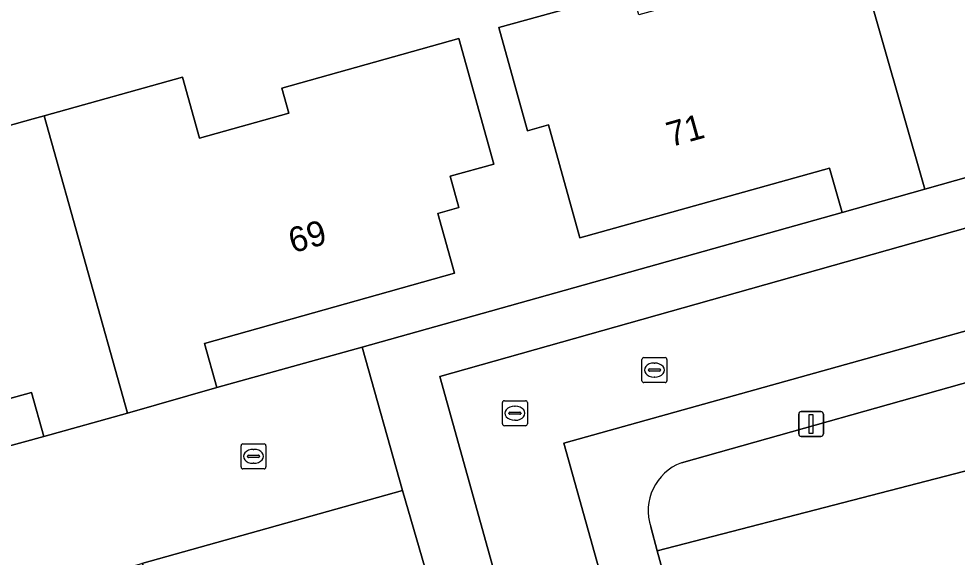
# Model space of a CAD drawing. Extents: x 159626 to 160723, y 388173 to 389416.
# Drawn here: x 159837.12 to 159874.74, y 388448.77 to 388470.35 of the extents above; entities that cross this region are included whole.
import ezdxf

# ---------------------------------------------------------------- set-up
doc = ezdxf.new("R2010")
doc.units = 0
for name, color, linetype in [('IMGEO_Erf', 7, 'Continuous'), ('IMGEO_Groenvoorziening', 7, 'Continuous'), ('IMGEO_Kolk', 7, 'Continuous'), ('IMGEO_Lichtmast', 7, 'Continuous'), ('IMGEO_Pand', 7, 'Continuous'), ('IMGEO_Pand_nummerreeks', 7, 'Continuous'), ('IMGEO_Rijbaan_lokaal_open', 7, 'Continuous'), ('IMGEO_Rioolput', 7, 'Continuous'), ('IMGEO_Voetpad_open', 7, 'Continuous')]:
    doc.layers.add(name, color=color, linetype=linetype)

msp = doc.modelspace()

# ---------------------------------------------------------------- linework, layer by layer
at = {"layer": 'IMGEO_Erf'}
for points in [[(159832.881, 388464.987), (159837.696, 388466.335), (159838.145, 388466.461), (159843.685, 388468.012), (159844.37, 388465.564), (159847.946, 388466.564), (159847.664, 388467.566), (159854.756, 388469.551), (159856.163, 388464.528), (159854.41, 388464.037), (159854.76, 388462.785), (159853.92, 388462.55), (159854.591, 388460.15), (159844.567, 388457.342), (159845.063, 388455.568), (159850.882, 388457.196), (159870.121, 388462.581), (159869.615, 388464.359), (159859.613, 388461.567), (159858.355, 388466.092), (159857.517, 388465.859), (159856.365, 388469.998), (159861.708, 388471.483)], [(159894.206, 388461.135), (159890.882, 388460.201), (159881.289, 388457.505), (159876.398, 388456.13), (159863.681, 388452.556)], [(159819.193, 388448.425), (159838.132, 388453.605), (159837.634, 388455.378), (159823.372, 388451.431)], [(159862.457, 388449.987), (159862.717, 388449.025), (159879.836, 388453.469)]]:
    msp.add_lwpolyline(points, dxfattribs=at)
msp.add_arc((159864.399, 388450.638), 2.048, 110.5157, 198.5333, dxfattribs=at)
at = {"layer": 'IMGEO_Groenvoorziening'}
msp.add_lwpolyline([(159856.782, 388436.748), (159852.499, 388451.444), (159842.058, 388448.523), (159844.146, 388445.771)], dxfattribs=at)
at = {"layer": 'IMGEO_Kolk'}
for p, q in [((159862.102, 388455.847), (159862.102, 388456.699)), ((159862.177, 388456.773), (159863.029, 388456.773)), ((159863.103, 388456.699), (159863.103, 388455.847)), ((159862.361, 388456.267), (159862.361, 388456.279)), ((159862.404, 388456.316), (159862.802, 388456.316)), ((159862.59, 388456.553), (159862.615, 388456.553)), ((159862.845, 388456.279), (159862.845, 388456.267)), ((159862.799, 388456.23), (159862.401, 388456.23)), ((159862.613, 388455.993), (159862.588, 388455.993)), ((159863.029, 388455.773), (159862.177, 388455.773)), ((159846.031, 388452.39), (159846.031, 388453.242)), ((159846.106, 388453.316), (159846.958, 388453.316)), ((159847.032, 388453.242), (159847.032, 388452.39)), ((159846.333, 388452.859), (159846.731, 388452.859)), ((159846.519, 388453.096), (159846.544, 388453.096)), ((159846.29, 388452.81), (159846.29, 388452.822)), ((159846.728, 388452.773), (159846.33, 388452.773)), ((159846.542, 388452.536), (159846.517, 388452.536)), ((159846.774, 388452.822), (159846.774, 388452.81)), ((159846.958, 388452.316), (159846.106, 388452.316))]:
    msp.add_line(p, q, dxfattribs=at)
for points in [[(159862.102, 388455.847), (159862.102, 388456.699)], [(159862.177, 388456.773), (159863.029, 388456.773)], [(159863.103, 388456.699), (159863.103, 388455.847)], [(159863.029, 388455.773), (159862.177, 388455.773)], [(159846.031, 388452.39), (159846.031, 388453.242)], [(159846.106, 388453.316), (159846.958, 388453.316)], [(159847.032, 388453.242), (159847.032, 388452.39)], [(159846.958, 388452.316), (159846.106, 388452.316)]]:
    msp.add_lwpolyline(points, dxfattribs=at)
for centre, radius, start, end in [((159862.179, 388456.697), 0.0765, 91.552, 178.448), ((159862.179, 388456.697), 0.0765, 91.552, 178.448), ((159863.027, 388456.697), 0.0765, 1.552, 88.448), ((159863.027, 388456.697), 0.0765, 1.552, 88.448), ((159862.401, 388456.276), 0.0403, 85.8775, 175.7526), ((159862.398, 388456.266), 0.0366, 178.938, 274.7102), ((159862.802, 388456.273), 0.043, 264.8664, 352.4533), ((159862.806, 388456.278), 0.0386, 1.7309, 96.639), ((159862.179, 388455.849), 0.0765, 181.552, 268.448), ((159862.179, 388455.849), 0.0765, 181.552, 268.448), ((159863.027, 388455.849), 0.0765, 271.552, 358.448), ((159863.027, 388455.849), 0.0765, 271.552, 358.448), ((159846.108, 388453.24), 0.0765, 91.552, 178.448), ((159846.108, 388453.24), 0.0765, 91.552, 178.448), ((159846.956, 388453.24), 0.0765, 1.552, 88.448), ((159846.956, 388453.24), 0.0765, 1.552, 88.448), ((159846.33, 388452.819), 0.0403, 85.8775, 175.7526), ((159846.735, 388452.821), 0.0386, 1.7309, 96.639), ((159846.327, 388452.809), 0.0366, 178.938, 274.7102), ((159846.731, 388452.816), 0.043, 264.8664, 352.4533), ((159846.108, 388452.392), 0.0765, 181.552, 268.448), ((159846.108, 388452.392), 0.0765, 181.552, 268.448), ((159846.956, 388452.392), 0.0765, 271.552, 358.448), ((159846.956, 388452.392), 0.0765, 271.552, 358.448)]:
    msp.add_arc(centre, radius, start, end, dxfattribs=at)
for centre, major_axis, ratio, start_param, end_param in [((159862.589, 388456.273), (-0.387, 0.002), 0.722429, 4.712389, 7.853982), ((159862.614, 388456.273), (-0.39, 0.002), 0.717154, 1.570796, 4.712389), ((159846.518, 388452.816), (-0.387, 0.002), 0.722429, 4.712389, 7.853982), ((159846.543, 388452.816), (-0.39, 0.002), 0.717154, 1.570796, 4.712389)]:
    msp.add_ellipse(centre, major_axis=major_axis, ratio=ratio, start_param=start_param, end_param=end_param, dxfattribs=at)
at = {"layer": 'IMGEO_Lichtmast'}
for p, q in [((159868.384, 388453.712), (159868.384, 388454.512)), ((159868.384, 388454.512), (159868.384, 388453.712)), ((159868.484, 388454.612), (159869.274, 388454.612)), ((159869.274, 388454.612), (159868.484, 388454.612)), ((159869.374, 388454.512), (159869.374, 388453.712)), ((159869.374, 388453.712), (159869.374, 388454.512)), ((159869.274, 388453.612), (159868.484, 388453.612)), ((159868.484, 388453.612), (159869.274, 388453.612))]:
    msp.add_line(p, q, dxfattribs=at)
msp.add_lwpolyline([(159868.804, 388454.487), (159868.954, 388454.487), (159868.954, 388453.737), (159868.804, 388453.737), (159868.804, 388454.487)], dxfattribs=at)
for centre, start, end in [((159868.484, 388454.512), 90, 180), ((159868.484, 388454.512), 90, 180), ((159869.274, 388454.512), 0, 90), ((159869.274, 388454.512), 360, 90), ((159868.484, 388453.712), 180, 270), ((159868.484, 388453.712), 180, 270), ((159869.274, 388453.712), 270, 0), ((159869.274, 388453.712), 270, 0)]:
    msp.add_arc(centre, 0.1, start, end, dxfattribs=at)
at = {"layer": 'IMGEO_Pand'}
for points in [[(159870.052, 388475.377), (159873.439, 388463.52), (159877.039, 388464.539), (159876.552, 388466.292), (159886.556, 388469.073), (159885.3, 388473.598), (159886.138, 388473.831), (159884.99, 388477.962), (159879.657, 388476.48), (159879.933, 388475.489), (159876.343, 388474.49), (159875.663, 388476.937), (159870.846, 388475.598)], [(159870.052, 388475.377), (159864.871, 388473.937), (159865.552, 388471.493), (159861.98, 388470.501), (159861.708, 388471.483), (159856.365, 388469.998), (159857.517, 388465.859), (159858.355, 388466.092), (159859.613, 388461.567), (159869.615, 388464.359), (159870.121, 388462.581), (159873.439, 388463.52)], [(159841.477, 388454.552), (159845.063, 388455.568), (159844.567, 388457.342), (159854.591, 388460.15), (159853.92, 388462.55), (159854.76, 388462.785), (159854.41, 388464.037), (159856.163, 388464.528), (159854.756, 388469.551), (159847.664, 388467.566), (159847.946, 388466.564), (159844.37, 388465.564), (159843.685, 388468.012), (159838.145, 388466.461)], [(159841.477, 388454.552), (159838.145, 388466.461), (159837.696, 388466.335), (159832.881, 388464.987), (159832.487, 388466.391), (159828.906, 388465.387), (159824.145, 388464.052), (159824.948, 388461.189), (159824.359, 388461.024), (159824.966, 388458.858), (159821.576, 388457.92), (159823.372, 388451.431), (159837.634, 388455.378), (159838.132, 388453.605)], [(159863.708, 388445.396), (159865.486, 388445.857), (159868.091, 388435.822), (159872.633, 388437.002), (159872.849, 388436.17), (159876.985, 388437.244), (159875.591, 388442.607), (159877.74, 388443.164), (159876.811, 388446.741), (159881.283, 388447.902), (159881.094, 388448.63), (159879.836, 388453.469), (159862.717, 388449.025)]]:
    msp.add_lwpolyline(points, close=True, dxfattribs=at)
at = {"layer": 'IMGEO_Rijbaan_lokaal_open'}
msp.add_lwpolyline([(159871.183, 388409.697), (159858.976, 388453.345), (159890.351, 388462.109), (159889.278, 388465.962), (159854.007, 388456.02), (159867.243, 388408.503)], close=True, dxfattribs=at)
msp.add_lwpolyline([(159826.869, 388444.275), (159840.008, 388447.95), (159842.058, 388448.523), (159852.499, 388451.444), (159850.882, 388457.196), (159845.063, 388455.568), (159841.477, 388454.552), (159838.132, 388453.605), (159819.193, 388448.425)], dxfattribs=at)
at = {"layer": 'IMGEO_Rioolput'}
for p, q in [((159856.511, 388454.116), (159856.511, 388454.968)), ((159856.586, 388455.042), (159857.438, 388455.042)), ((159856.999, 388454.822), (159857.024, 388454.822)), ((159857.512, 388454.968), (159857.512, 388454.116)), ((159856.77, 388454.536), (159856.77, 388454.548)), ((159857.208, 388454.499), (159856.81, 388454.499)), ((159856.813, 388454.585), (159857.211, 388454.585)), ((159857.254, 388454.548), (159857.254, 388454.536)), ((159857.438, 388454.042), (159856.586, 388454.042)), ((159857.022, 388454.262), (159856.997, 388454.262))]:
    msp.add_line(p, q, dxfattribs=at)
for points in [[(159856.511, 388454.116), (159856.511, 388454.968)], [(159856.586, 388455.042), (159857.438, 388455.042)], [(159857.512, 388454.968), (159857.512, 388454.116)], [(159857.438, 388454.042), (159856.586, 388454.042)]]:
    msp.add_lwpolyline(points, dxfattribs=at)
for centre, radius, start, end in [((159856.588, 388454.966), 0.0765, 91.552, 178.448), ((159856.588, 388454.966), 0.0765, 91.552, 178.448), ((159857.436, 388454.966), 0.0765, 1.552, 88.448), ((159857.436, 388454.966), 0.0765, 1.552, 88.448), ((159856.81, 388454.545), 0.0403, 85.8775, 175.7526), ((159856.807, 388454.535), 0.0366, 178.938, 274.7102), ((159857.211, 388454.542), 0.043, 264.8664, 352.4533), ((159857.215, 388454.547), 0.0386, 1.7309, 96.639), ((159856.588, 388454.118), 0.0765, 181.552, 268.448), ((159856.588, 388454.118), 0.0765, 181.552, 268.448), ((159857.436, 388454.118), 0.0765, 271.552, 358.448), ((159857.436, 388454.118), 0.0765, 271.552, 358.448)]:
    msp.add_arc(centre, radius, start, end, dxfattribs=at)
for centre, major_axis, ratio, start_param, end_param in [((159856.998, 388454.542), (-0.387, 0.002), 0.722429, 4.712389, 7.853982), ((159857.023, 388454.542), (-0.39, 0.002), 0.717154, 1.570796, 4.712389)]:
    msp.add_ellipse(centre, major_axis=major_axis, ratio=ratio, start_param=start_param, end_param=end_param, dxfattribs=at)
at = {"layer": 'IMGEO_Voetpad_open'}
for points in [[(159890.763, 388466.088), (159889.278, 388465.962), (159890.351, 388462.109), (159858.976, 388453.345), (159871.183, 388409.697), (159871.974, 388406.867), (159883.064, 388367.211), (159868.371, 388363.142), (159877.583, 388329.947), (159898.714, 388335.876), (159901.439, 388336.64), (159939.056, 388347.194), (159938.495, 388349.196), (159935.001, 388348.184)], [(159877.981, 388369.955), (159868.033, 388405.666), (159867.243, 388408.503), (159854.007, 388456.02), (159889.278, 388465.962)], [(159877.039, 388464.539), (159873.439, 388463.52), (159870.121, 388462.581), (159850.882, 388457.196), (159852.499, 388451.444), (159856.782, 388436.748), (159858.925, 388429.04), (159860.545, 388423.261), (159861.857, 388418.591), (159861.923, 388418.609), (159863.885, 388411.505), (159866.166, 388403.253), (159869.862, 388390.097), (159870.943, 388386.198), (159871.789, 388383.149), (159874.651, 388372.898)], [(159863.681, 388452.556), (159876.398, 388456.13), (159881.289, 388457.505), (159890.882, 388460.201), (159894.206, 388461.135)], [(159872.396, 388362.2), (159916.97, 388374.672), (159922.592, 388376.25), (159928.443, 388377.878), (159927.612, 388380.783), (159906.895, 388374.924), (159895.473, 388371.693), (159891.335, 388370.601), (159885.125, 388368.905), (159881.588, 388381.462), (159880.723, 388384.547), (159879.649, 388388.378), (159872.648, 388413.43), (159871.81, 388416.443), (159870.719, 388420.363), (159863.708, 388445.396), (159862.717, 388449.025), (159862.457, 388449.987)]]:
    msp.add_lwpolyline(points, dxfattribs=at)
msp.add_arc((159864.399, 388450.638), 2.048, 110.5157, 198.5333, dxfattribs=at)

# ---------------------------------------------------------------- texts
at = {"layer": 'IMGEO_Pand_nummerreeks'}
for s, rotation, p in [('71', 15.5968, (159863.249, 388465.198)), ('69', 15.649, (159848.104, 388460.95))]:
    msp.add_text(s, height=1, rotation=rotation, dxfattribs=at).set_placement(p)

doc.saveas('drawing.dxf')
